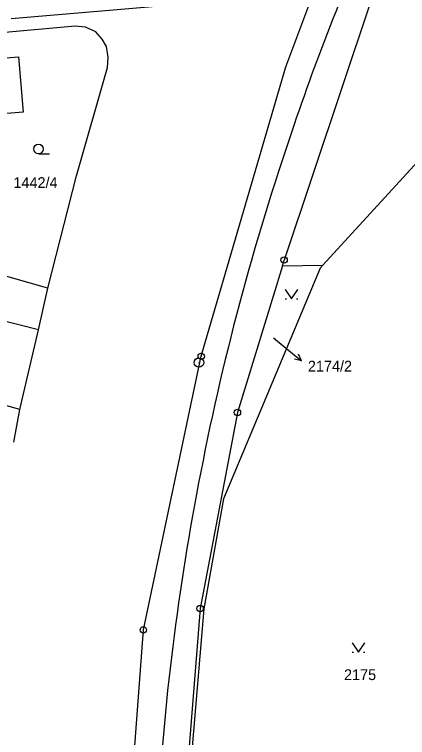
# Model space of a CAD drawing. Extents: x -795483 to -789093, y -1112258 to -1108741.
# Drawn here: x -792641.5 to -792579.5, y -1110275.1 to -1110161.2 of the extents above; entities that cross this region are included whole.
import ezdxf

# ---------------------------------------------------------------- set-up
doc = ezdxf.new("R2010")
doc.units = 0
for name, color, linetype in [('Komunikace', 7, 'Continuous'), ('Vrstva 1', 7, 'Continuous'), ('Vrstva 10', 7, 'Continuous'), ('Vrstva 14', 7, 'Continuous'), ('Vrstva 16', 7, 'Continuous'), ('Vrstva 23', 7, 'Continuous'), ('Vrstva 28', 7, 'Continuous')]:
    doc.layers.add(name, color=color, linetype=linetype)

msp = doc.modelspace()

# ---------------------------------------------------------------- linework, layer by layer
at = {"layer": 'Komunikace'}
msp.add_line((-792600.65, -1110212.11), (-792598.56, -1110213.83), dxfattribs=at)
at = {"layer": 'Vrstva 1'}
for p, q in [((-792598.72, -1110169.4), (-792594.35, -1110157.78)), ((-792641.97, -1110161.78), (-792616.04, -1110159.6)), ((-792585.44, -1110159.39), (-792598.98, -1110199.86)), ((-792631.9, -1110162.99), (-792650.59, -1110164.71)), ((-792630.27, -1110163.16), (-792631.9, -1110162.99)), ((-792628.66, -1110163.9), (-792630.27, -1110163.16)), ((-792627.67, -1110165.03), (-792628.66, -1110163.9)), ((-792626.94, -1110166.21), (-792627.67, -1110165.03)), ((-792626.68, -1110167.87), (-792626.94, -1110166.21)), ((-792650.4, -1110168.59), (-792640.81, -1110167.82)), ((-792640.81, -1110167.82), (-792640.09, -1110176.54)), ((-792626.82, -1110169.51), (-792626.68, -1110167.87)), ((-792631.71, -1110186.61), (-792626.82, -1110169.51)), ((-792612.04, -1110215.02), (-792598.72, -1110169.4)), ((-792640.09, -1110176.54), (-792643.28, -1110176.8)), ((-792574.54, -1110180.58), (-792592.91, -1110200.68)), ((-792636.2, -1110204.31), (-792631.71, -1110186.61)), ((-792599.26, -1110200.78), (-792598.98, -1110199.86)), ((-792599.26, -1110200.78), (-792606.33, -1110223.88)), ((-792599.26, -1110200.78), (-792592.91, -1110200.68)), ((-792592.91, -1110200.68), (-792593.31, -1110201.12)), ((-792636.2, -1110204.31), (-792645.67, -1110201.59)), ((-792593.31, -1110201.12), (-792608.53, -1110237.49)), ((-792637.65, -1110210.85), (-792636.2, -1110204.31)), ((-792637.65, -1110210.85), (-792647.48, -1110208.4)), ((-792640.62, -1110223.39), (-792637.65, -1110210.85)), ((-792621.16, -1110258.14), (-792612.04, -1110215.02)), ((-792640.62, -1110223.39), (-792657.62, -1110218.56)), ((-792641.57, -1110228.57), (-792640.62, -1110223.39)), ((-792606.33, -1110223.88), (-792612.21, -1110254.77)), ((-792608.53, -1110237.49), (-792611.62, -1110254.8)), ((-792612.21, -1110254.77), (-792615.1, -1110291.3)), ((-792611.62, -1110254.8), (-792614.73, -1110291.32)), ((-792624.38, -1110302.15), (-792621.16, -1110258.14))]:
    msp.add_line(p, q, dxfattribs=at)
at = {"layer": 'Vrstva 10'}
for centre, radius, start, end in [((-792268.48, -1110289.53), 347.15, 155.4901, 161.7343), ((-792219.95, -1110309.44), 399.5, 161.2038, 169.5195), ((-792228.65, -1110309.08), 390.88, 169.3386, 177.4817)]:
    msp.add_arc(centre, radius, start, end, dxfattribs=at)
at = {"layer": 'Vrstva 16'}
for p, q in [((-792598.56, -1110213.83), (-792596.24, -1110215.73)), ((-792596.24, -1110215.73), (-792596.7, -1110214.71)), ((-792596.24, -1110215.73), (-792597.33, -1110215.49))]:
    msp.add_line(p, q, dxfattribs=at)
at = {"layer": 'Vrstva 23'}
for p, q in [((-792637.67, -1110183.1), (-792635.92, -1110183.1)), ((-792598.82, -1110204.49), (-792597.82, -1110205.99)), ((-792597.82, -1110205.99), (-792596.82, -1110204.49)), ((-792598.82, -1110205.99), (-792598.62, -1110205.99)), ((-792597.02, -1110205.99), (-792596.82, -1110205.99)), ((-792588.28, -1110260.17), (-792587.28, -1110261.67)), ((-792587.28, -1110261.67), (-792586.28, -1110260.17)), ((-792588.28, -1110261.67), (-792588.08, -1110261.67)), ((-792586.48, -1110261.67), (-792586.28, -1110261.67))]:
    msp.add_line(p, q, dxfattribs=at)
msp.add_circle((-792637.67, -1110182.35), 0.75, dxfattribs=at)
at = {"layer": 'Vrstva 28'}
for centre, radius in [((-792598.98, -1110199.86), 0.5), ((-792598.98, -1110199.86), 0.01), ((-792612.04, -1110215.02), 0.5), ((-792612.4, -1110216.01), 0.75), ((-792612.04, -1110215.02), 0.01), ((-792612.4, -1110216.01), 0.01), ((-792606.33, -1110223.88), 0.5), ((-792606.33, -1110223.88), 0.01), ((-792612.21, -1110254.77), 0.5), ((-792612.21, -1110254.77), 0.01), ((-792621.16, -1110258.14), 0.5), ((-792621.16, -1110258.14), 0.01)]:
    msp.add_circle(centre, radius, dxfattribs=at)

# ---------------------------------------------------------------- texts
at = {"layer": 'Vrstva 14'}
for s, height, p in [('1442/4', 1.7, (-792641.62, -1110188.5)), ('2174/2', 0.1, (-792600.65, -1110212.11)), ('2175', 1.7, (-792589.55, -1110266.05))]:
    msp.add_text(s, height=height, dxfattribs=at).set_placement(p)
at = {"layer": 'Vrstva 16'}
msp.add_text('2174/2', height=1.7, dxfattribs=at).set_placement((-792595.24, -1110217.43))

doc.saveas('drawing.dxf')
